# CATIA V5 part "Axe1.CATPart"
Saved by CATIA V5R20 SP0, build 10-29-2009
Part number: Axe1
Bounding box of the stored display mesh (mm): x -9.5 to -2.5, y 27 to 34, z -18 to -3.5
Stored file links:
  E:\Boulot\SeaTech\2eme ANNEE\FabricationAdditive\TP_MOSM_CREM\Projet Sauterelle de serrage\CAO Assemblage Sauterelle\Axe1.CATPart
  E:\Boulot\SeaTech\2eme ANNEE\FabricationAdditive\TP_MOSM_CREM\Projet Sauterelle de serrage\CAO Assemblage Sauterelle\Sauterelle_horizontale_05120-06.CATPart
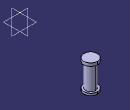
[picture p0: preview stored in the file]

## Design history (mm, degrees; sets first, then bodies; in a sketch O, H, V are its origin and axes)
Body1 (main body)
  Solid1 "05120-06_4": solid without history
